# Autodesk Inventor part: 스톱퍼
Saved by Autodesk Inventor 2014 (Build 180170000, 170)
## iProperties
Created: 2026-09
Part Number: 스톱퍼
Material: 일반
Document SubType Name: Modeling
Designer: dg
Density: 1 g/cm^3
Appearance: 기본값
Author: dg
Author: jhkim
Creation Date: 2026-08-27
Sending System: Autodesk Inventor 2027
Preprocessor: ST-DEVELOPER v20.1
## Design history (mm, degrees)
node "스톱퍼1"
node "솔리드1"
node "기준1"
